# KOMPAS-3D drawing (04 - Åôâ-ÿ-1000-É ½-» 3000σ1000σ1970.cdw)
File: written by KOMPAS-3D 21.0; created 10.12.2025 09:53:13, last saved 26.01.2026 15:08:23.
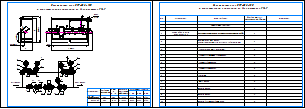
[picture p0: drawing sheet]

Sheets 1-2: A3, landscape

Document properties: Автор: RaskoAdmin; Форматы листов документа: 2xA3; Полное имя файла: \\ur38nt01\Departments\КТО\КБ ПУРДГ\Заявки\Прайс-лист на типовые шкафы ГРПШ\ПУГ-Ш-1000-Р л-п 3000х1000х1970.cdw

Title block, sheet 1: sheet number: 1; Количество листов документа: 2; Форматы листов документа: A3; stored path: \\ur38nt01\Departments\КТО\КБ ПУРДГ\Заявки\Прайс-лист на типовые шкафы ГРПШ\ПУГ-ШУЭО-65-Р л-п.cdw
Title block, sheet 2: sheet number: 2

Views: Вид 1
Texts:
  Условный
  проход Ду, мм
  Qmax,
  Диапазон
  измерений
  Qmin/Qmax
  Габаритные размеры
  А, мм
  В, мм
  Н, мм
  ПУГ-Ш-650-Р
  Пункт учета газа ПУГ-Ш Ду150
  с измерительным комплексом на базе счетчика РГ-Р
  Вход Ду150
  Выход Ду150
  Поз.
  Условный проход
  расходомера Ду 150, мм
  СГ-ЭК-Р-(0,2...2,0)-
  Стандартные изделия
  Измерительный комплекс с ротационным счетчиком Ду150
  Фильтр газа ФГ Ду150
  (Оснащен индикатором перепада давления ДПД)
  Кран кнопочный под манометр
  Кран шаровой штуцерный Ду20
  Кран шаровый Ду125
  Кран шаровый Ду150
  Манометр
  Отвод Ду125
  Фланец Ду125
  Фланец Ду150
  Фланец воротниковый Ду125
  Ду20
  Свеча
  POLYLINE_STYLE_0.18_RGB_0_0_0
  POLYLINE_STYLE_0.77_RGB_0_0_0
  PHANTOM_RGB_255_0_191_SC_1_THICK_0.15
  СONTINUOUS_RGB_0_0_0_THICK_0.25
  K5LT32768_RGB_0_0_0_THICK_0.25
  K5LT32769_RGB_128_128_128_THICK_0.25
  K5LT32770_RGB_0_0_0_THICK_0.7
  ACISOTGL_RGB_255_0_0_SC_1_THICK_0.2
  POLYLINE_STYLE_0.50_RGB_0_0_0
  ACISOTGL_RGB_0_0_0_SC_1_THICK_0.18
  ACISOTGL_RGB_0_0_0_SC_1_THICK_0.15
  Без основной надписи.
Dimensions and other numbers on the sheet: 150; 650; 4/1000; 3000; 1000; 1960; -1000-Р; 6/1000; 1; 2; 4; 400; 350; 800±100; 450; 3; 5; 6; 7; 8; 9; 10; 11; -650 (1000)/1,6; 1:15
